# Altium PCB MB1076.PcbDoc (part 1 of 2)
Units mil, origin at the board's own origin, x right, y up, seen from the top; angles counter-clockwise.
Board outline 2200 x 4400 mil, 2 copper layers (TOP, Bottom), stack 60.433 mil thick; 144 components, 144 nets, 518 pads, 266 vias.
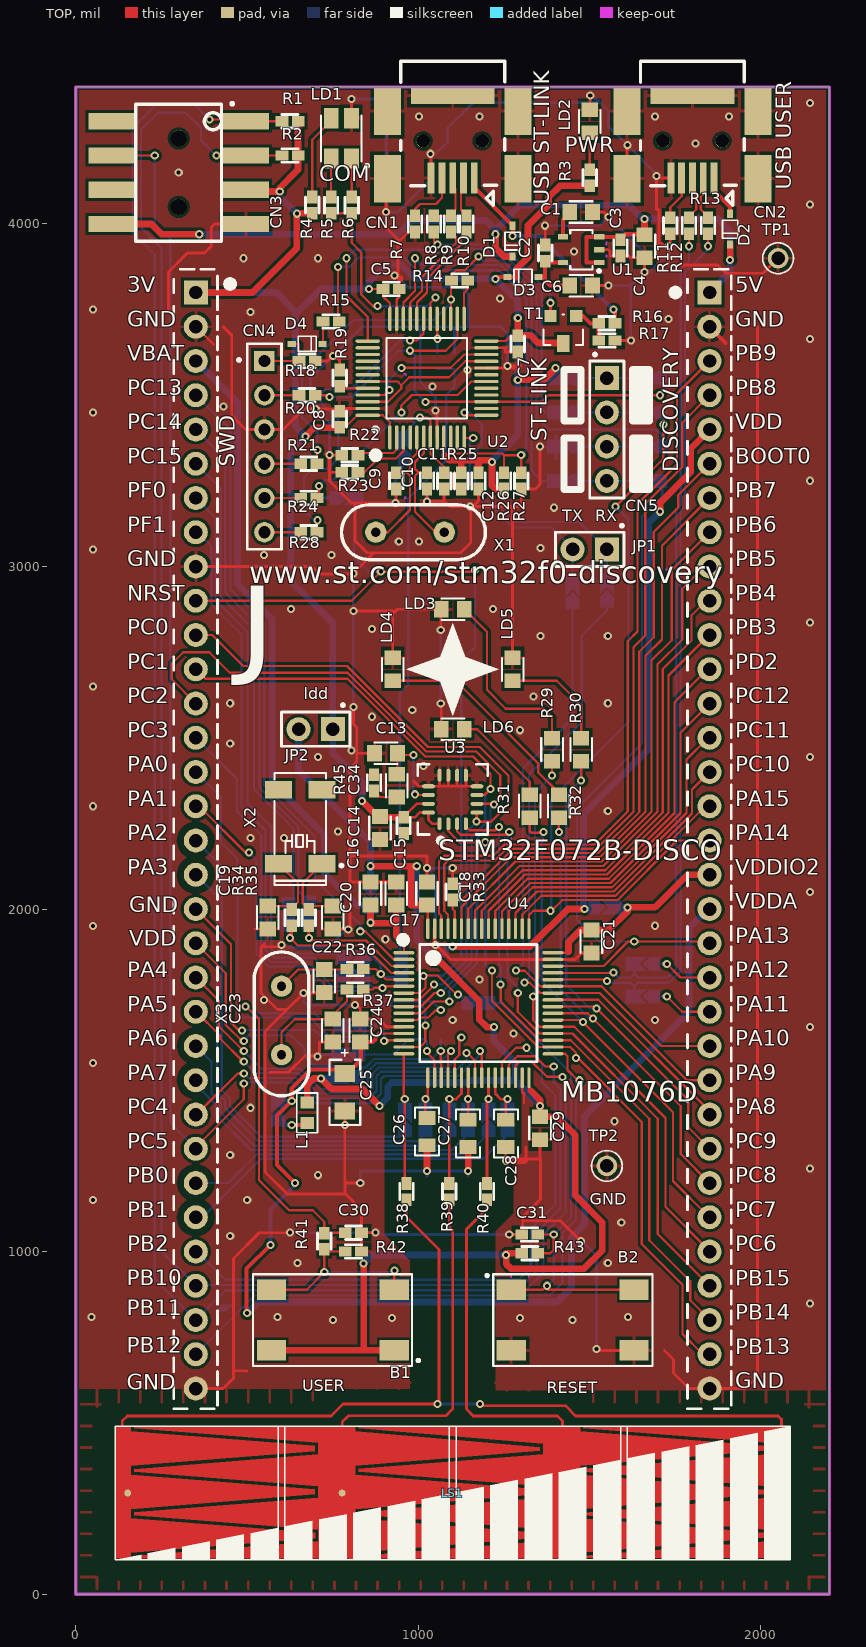
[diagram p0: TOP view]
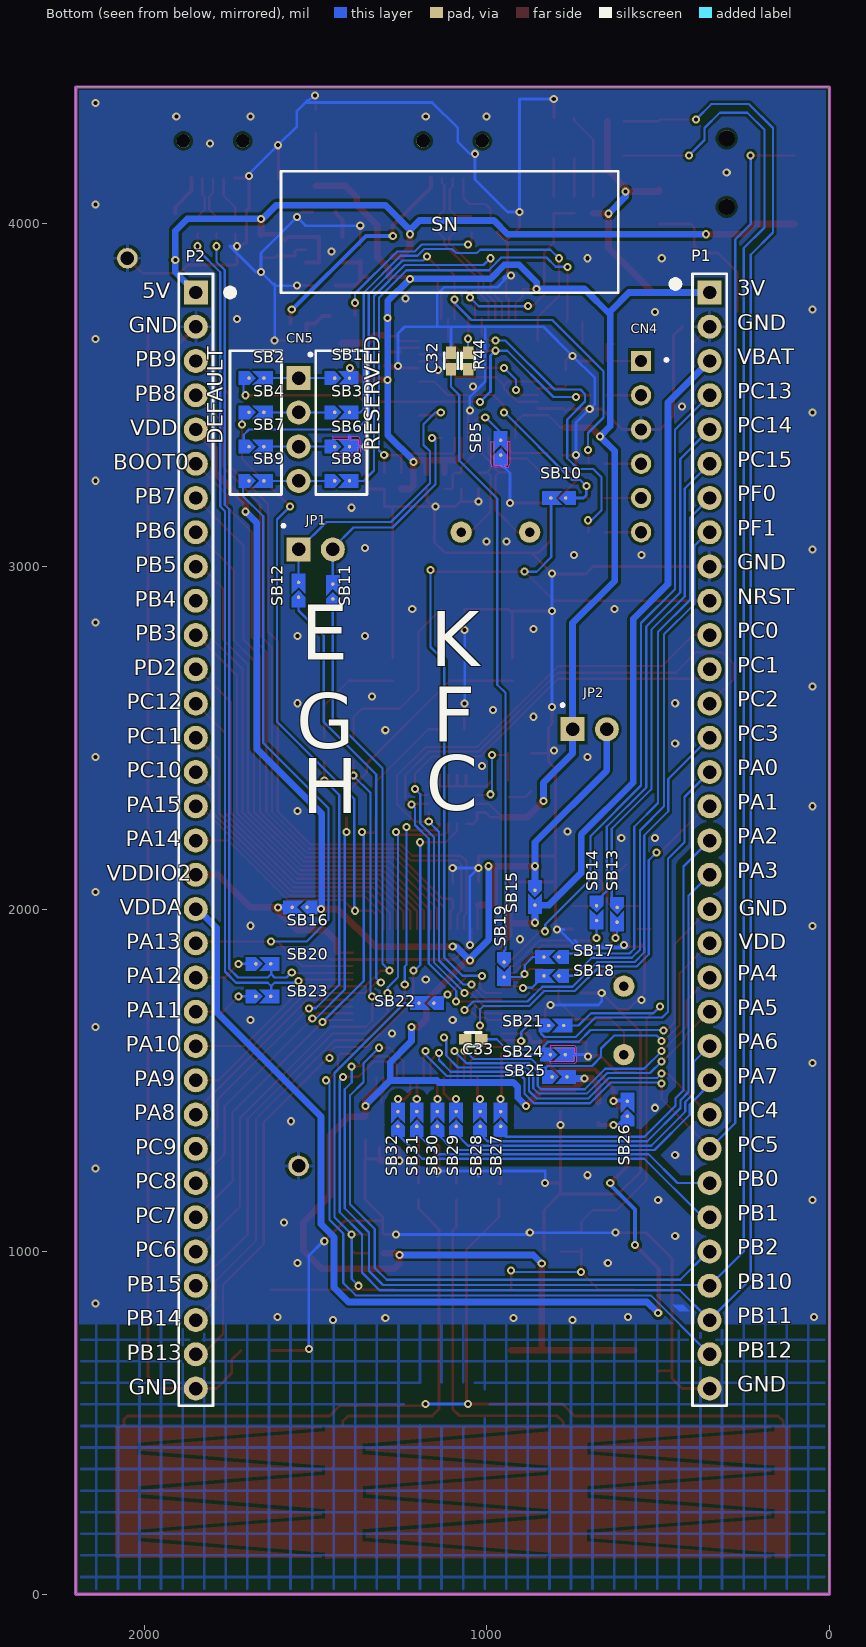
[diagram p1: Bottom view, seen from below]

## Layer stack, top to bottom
Top Mask: solder mask 0.4, Solder Resist, Dk 3.5
TOP: signal copper 1.3779
Dielectric 1: dielectric 57.6772, FR-4, Dk 4.8
Bottom: signal copper 1.3779
Bottom Solder: solder mask 0.4, Solder Resist, Dk 3.5

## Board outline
0,0 2200,0 2200,4400 0,4400

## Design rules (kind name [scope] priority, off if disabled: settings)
BoardOutlineClearance [All and not (IsPad and ((Name = 'CN1-6') or (Name = 'CN2-6') or (Name = 'CN1-7') or (Name = 'CN2-7'))) and not OnSilkscreen] p1: gap=10 ignorepadtopadclearanceinfootprint=FALSE except(0: Arc-SplitContinuation Track-SplitContinuation SMDPad-SplitContinuation THPad-SplitContinuation Via-SplitContinuation Fill-SplitContinuation Poly-SplitContinuation Region-SplitContinuation Text-SplitContinuation)
Clearance Clearance_Keepout [IsKeepout] p1: gap=0 ignorepadtopadclearanceinfootprint=FALSE
Clearance Clearance_ESPACE_0.5 [InNetClass('ESPACE_0.5') vs InPolygon] p2: gap=19.68 ignorepadtopadclearanceinfootprint=FALSE except(0: Arc-Hole Track-Hole SMDPad-Hole THPad-Hole Via-Hole Fill-Hole Poly-Hole Region-Hole Text-Hole)
Clearance Clearance_LS_P1 [InNet('LS_P1') vs InPolygon and OnBottomLayer] p3: gap=48.03 ignorepadtopadclearanceinfootprint=FALSE except(0: Arc-Hole Track-Hole SMDPad-Hole THPad-Hole Via-Hole Fill-Hole Poly-Hole Region-Hole Text-Hole; 55.91: Arc-Fill Arc-Poly Arc-Region Track-Fill Track-Poly Track-Region)
Clearance Clearance_CN1_CN2 [IsPad and ((Name = 'CN1-6') or (Name = 'CN2-6')) vs IsKeepout] p4: gap=0 ignorepadtopadclearanceinfootprint=FALSE
Clearance CopperToBoard [InPolygon vs IsBoardOutline] p5: gap=9.84 ignorepadtopadclearanceinfootprint=FALSE except(0: Arc-Hole Track-Hole SMDPad-Hole THPad-Hole Via-Hole Fill-Hole Poly-Hole Region-Hole Text-Hole)
Clearance "Clearance_Pont citroen" [HasFootprint('JP2_SMD (Primary)') and IsComponentPrimitive and IsRegion vs HasFootprint('JP2_SMD (Primary)') and IsComponentPrimitive and IsRegion] p6: gap=3.94 ignorepadtopadclearanceinfootprint=FALSE except(0: Arc-Hole Track-Hole SMDPad-Hole THPad-Hole Via-Hole Fill-Hole Poly-Hole Region-Hole Text-Hole)
Clearance [All] p7: gap=5.91 ignorepadtopadclearanceinfootprint=FALSE except(0: Arc-Hole Track-Hole SMDPad-Hole THPad-Hole Via-Hole Fill-Hole Poly-Hole Region-Hole Text-Hole; 6.93: Fill-Fill Fill-Poly Fill-Region Poly-Poly Poly-Region Region-Region; 8.27: Arc-Fill Arc-Poly Arc-Region Track-Fill Track-Poly Track-Region SMDPad-Fill SMDPad-Poly SMDPad-Region THPad-Fill THPad-Poly THPad-Region Via-Fill Via-Poly Via-Region)
ComponentClearance [All and not HasFootprint('VIA')] p1: gap=3.94 collisioncheckmode=3 verticalgap=10 showdistances=FALSE
MinimumSolderMaskSliver [All] p1: minsoldermaskwidth=3.94
PolygonConnect PolygonConnect_1 [IsPad and ((Name = 'P1-33') or (Name = 'P2-33'))] p1: connectstyle=Direct reliefconductorwidth=10 reliefentries=4 polygonreliefangle="90 Angle" airgapwidth=10
PolygonConnect "PolygonConnect_Via comp" [IsVia] p2: connectstyle=Direct reliefconductorwidth=10 reliefentries=4 polygonreliefangle="90 Angle" airgapwidth=10
PolygonConnect [All] p3: connectstyle=Relief reliefconductorwidth=10 reliefentries=4 polygonreliefangle="90 Angle" airgapwidth=10
RoutingVias [All] p1: holewidth=11.81 width=23.62 viastyle="Through Hole" minholewidth=11.81 minwidth=23.62 maxholewidth=11.81 maxwidth=23.62
SolderMaskExpansion SolderMaskExpansion_via [HasFootprint('via') or IsVia] p1: expansion=-39.37
SolderMaskExpansion [All] p2: expansion=1.97
Width [All] p1: maxlimit=78.74 minlimit=5.91 preferedwidth=6.5
28 further rules are at their usual default settings.

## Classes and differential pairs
component class MB1076C: P1 P2
component class U_MEMS_USB: C13 C14 C15 C34 CN2 CN3 D2 LD3 LD4 LD5 LD6 R1 R2 R11 R12 R13 R29 R30 R31 R32 R45 TP1 TP2 U3
component class U_SENSOR_PB: B1 B2 C26 C27 C28 C30 C31 LS1 R38 R39 R40 R41 R42 R43 SB21 SB22
component class U_ST_LINK: C1 C2 C3 C4 C5 C6 C7 C8 C9 C10 C11 C12 C32 CN1 CN4 CN5 D1 D3 D4 JP1 JP2 LD1 LD2 R3 R4 R5 R6 R7 R8 R9 R10 R14 R15 R16 R17 R18 R19 R20 R21 R22 R23 R24 R25 R26 R27 R28 R44 SB1 SB2 SB3 SB4 SB5 SB6 SB7 SB8 SB9 SB10 SB11 SB12 T1 U1 U2 X1
component class U_STM32Fx: C16 C17 C18 C19 C20 C21 C22 C23 C24 C25 C29 C33 L1 R33 R34 R35 R36 R37 SB13 SB14 SB15 SB16 SB17 SB18 SB19 SB20 SB23 SB24 SB25 SB26 SB27 SB28 SB29 SB30 SB31 SB32 U4 X2 X3
net class ESPACE_0.5: PA2 PA3 PA6 PA7 PB0 PB1 TS_G1_IO3 TS_G1_IO4 TS_G2_IO3 TS_G2_IO4 TS_G3_IO2 TS_G3_IO3

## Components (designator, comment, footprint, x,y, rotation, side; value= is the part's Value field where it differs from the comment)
B1 "SW-PUSH-CMS" BP1CMS 750,800 r90 top locked
B2 "SW-PUSH-CMS" BP1CMS 1450,800 r270 top
C1 "10nF_X7R_0603" 0603C 1475,4035 r180 top value=10NF
C2 "100nF" 0402C 1370,3915 r0 top
C3 "100nF" 0402C 1590,3930 r180 top
C4 "1µF_X5R_0603" 0603C 1660,3935 r90 top value=1µF
C5 "100nF" 0402C 920,3810 r270 top
C6 "1µF_X5R_0603" 0603C 1475,3820 r0 top value=1µF
C7 "100nF" 0402C 1290,3650 r180 top
C8 "100nF" 0402C 770,3430 r0 top
C9 "20pF" 0402C 935,3250 r0 top value=100nF
C10 "20pF" 0402C 1025,3250 r0 top value=100nF
C11 "100nF" 0402C 1075,3250 r180 top
C12 "100nF" 0402C 1175,3250 r180 top
C13 "10nF/25V" 0603C 905,2455 r0 top value=100nF
C14 "10uF" 0603C 887.8,2236.22 r90 top value=100nF
C15 "100nF" 0402C 956.69,2244.09 r180 top
C16 "1uF" 0603C 860,2045 r90 top
C17 "100nF" 0603C 935,2045 r270 top
C18 "100nF" 0603C 1025,2045 r90 top
C19 "6.8pF" 0603C 560,1975 r270 top
C20 "6.8pF" 0603C 750,1975 r270 top
C21 "100nF" 0603C 1505,1905 r90 top
C22 "20pF" 0603C 725,1790 r90 top
C23 "20pF" 0603C 750,1645 r90 top
C24 "100nF" 0603C 830,1645 r270 top
C25 "1uF" CASE-AA 785,1465 r90 top value=10uF
C26 "47nF" 0805C 1025,1350 r270 top
C27 "47nF" 0805C 1145,1345 r270 top
C28 "47nF" 0805C 1255,1345 r270 top
C29 "100nF" 0603C 1355,1360 r90 top
C30 "100nF" 0402C 810,1055 r270 top
C31 "100nF" 0402C 1325,1050 r90 top
C32 "20pF" 0402C 1105,3600 r180 bottom locked value=100nF
C33 "100nF" 0402C 1040,1620 r90 bottom locked
C34 "Capacitor" C0603 936.42,2360.24 r270 top value=470nF
CN1 "USB-MINI-typeB" USB-MINI-B-SMD 1100,4242.52 r0 top
CN2 "USB-MINI-typeB" USB-MINI-B-SMD 1800,4242.52 r0 top
CN3 "SSM-104-L-DH" SSM-104-L-DH 300,4150 r90 top
CN4 "Header 6" HDR1X6 550,3600 r270 top
CN5 "Header 4" "Header 4" 1550,3550 r270 top
D1 "BAT60JFILM" SOD323/A 1275,3950 r90 top
D2 "BAT60JFILM" SOD323/A 1910,3985 r90 top
D3 "BAT60JFILM" SOD323/A 1305,3845 r0 top
D4 "BAT60JFILM" SOD323/A 675,3650 r180 top
JP1 "JP2" SIP2/2.54 1550,3050 r180 top
JP2 "" SIP2/2.54 750,2525 r180 top
L1 "fcm1608-0603" 0603L 675,1405 r270 top value=100uH
LD1 "LD_BICOLOR_CMS" HSMF-A201 775,4250 r270 top
LD2 "LED, red" 0603D 1500,4300 r90 top
LD3 "LED, red" 0603D 1100,2875 r180 top
LD4 "LED, orange" 0603D 925,2700 r90 top
LD5 "LED, green" 0603D 1275,2700 r90 top
LD6 "LED, blue" 0603D 1100,2525 r180 top
LS1 "Linear Sensor" "Linear Sensor 3 electrodes" 1100,295 r0 top
P1 "Header 33" HDR1X33 350,3800 r270 bottom locked
P2 "Header 33" HDR1X33 1850,3800 r270 bottom locked
R1 "4K7" 0402R 625,4300 r90 top value=10K
R2 "4K7" 0402R 625,4200 r90 top value=10K
R3 "1K" 0402R 1500,4135 r0 top value=10K
R4 "0" 0402R 690,4055 r0 top value=10K
R5 "100" 0402R 745,4055 r180 top value=10K
R6 "100" 0402R 805,4055 r180 top value=10K
R7 "100K" 0402R 990,4000 r0 top value=10K
R8 "1K5" 0402R 1045,4000 r0 top value=10K
R9 "0" 0402R 1095,4000 r0 top value=10K
R10 "0" 0402R 1140,4000 r0 top value=10K
R11 "100K" 0402R 1735,3995 r0 top value=10K
R12 "0" 0402R 1790,3995 r0 top value=10K
R13 "0" 0402R 1845,3995 r0 top value=10K
R14 "100" 0402R 1120,3835 r270 top value=10K
R15 "[NA]" 0402R 745,3715 r90 top value=10K
R16 "10K" 0402R 1550,3710 r90 top
R17 "36K" 0402R 1550,3660 r270 top value=10K
R18 "10K" 0402R 675,3600 r90 top
R19 "100K" 0402R 770,3550 r0 top value=10K
R20 "22" 0402R 675,3500 r90 top value=10K
R21 "22" 0402R 680,3300 r90 top value=10K
R22 "10K" 0402R 800,3325 r90 top
R23 "[NA]" 0402R 800,3275 r90 top value=10K
R24 "22" 0402R 680,3200 r90 top value=10K
R25 "100K" 0402R 1125,3250 r180 top value=10K
R26 "4K7" 0402R 1250,3250 r180 top value=10K
R27 "4K7" 0402R 1300,3250 r180 top value=10K
R28 "22" 0402R 680,3100 r90 top value=10K
R29 "1K" 0603R 1390,2465 r90 top value=10K
R30 "330" 0603R 1475,2465 r90 top value=10K
R31 "510" 0603R 1325,2300 r90 top value=10K
R32 "1K" 0603R 1410,2300 r90 top value=10K
R33 "510" 0402R 1100,2050 r180 top value=10K
R34 "0" 0402R 630,1975 r180 top value=1K5
R35 "0" 0402R 680,1975 r180 top value=1K5
R36 "0" 0402R 815,1825 r270 top value=1K5
R37 "220" 0402R 815,1765 r270 top value=1K5
R38 "10K" 0402R 965,1175 r0 top
R39 "10K" 0402R 1090,1175 r0 top
R40 "10K" 0402R 1200,1175 r0 top
R41 "10K" 0402R 725,1030 r0 top
R42 "10K" 0402R 810,1000 r270 top
R43 "[NA]" 0402R 1325,995 r270 top value=10K
R44 "100" 0402R 1055,3600 r180 bottom locked value=10K
R45 "10K" 0402R 870.08,2368.11 r0 top
SB1 "Circuit Breaker" JP2_SMD 1425,3550 r180 bottom locked
SB2 "Circuit Breaker" JP2_SMD 1675,3550 r180 bottom locked
SB3 "Circuit Breaker" JP2_SMD 1425,3450 r180 bottom locked
SB4 "Circuit Breaker" JP2_SMD 1675,3450 r180 bottom locked
SB5 "Circuit Breaker" JP2_SMD 960,3345 r90 bottom locked
SB6 "Circuit Breaker" JP2_SMD 1425,3350 r180 bottom locked
SB7 "Circuit Breaker" JP2_SMD 1675,3350 r180 bottom locked
SB8 "Circuit Breaker" JP2_SMD 1425,3250 r180 bottom locked
SB9 "Circuit Breaker" JP2_SMD 1675,3250 r180 bottom locked
SB10 "Circuit Breaker" JP2_SMD 790,3200 r0 bottom locked
SB11 "Circuit Breaker" JP2_SMD 1450,2925 r90 bottom locked
SB12 "Circuit Breaker" JP2_SMD 1550,2930 r90 bottom locked
SB13 "Circuit Breaker" JP2_SMD 620,1985 r270 bottom locked
SB14 "Circuit Breaker" JP2_SMD 680,1990 r270 bottom locked
SB15 "Circuit Breaker" JP2_SMD 860,2035 r270 bottom locked
SB16 "Circuit Breaker" JP2_SMD 1545,2005 r0 bottom locked
SB17 "Circuit Breaker" JP2_SMD 810,1860 r0 bottom locked
SB18 "Circuit Breaker" JP2_SMD 810,1805 r0 bottom locked
SB19 "Circuit Breaker" JP2_SMD 950,1825 r270 bottom locked
SB20 "Circuit Breaker" JP2_SMD 1655,1840 r180 bottom locked
SB21 "Circuit Breaker" JP2_SMD 800,1660 r180 bottom locked
SB22 "Circuit Breaker" JP2_SMD 1175,1725 r0 bottom locked
SB23 "Circuit Breaker" JP2_SMD 1655,1745 r180 bottom locked
SB24 "Circuit Breaker" JP2_SMD 795,1575 r180 bottom
SB25 "Circuit Breaker" JP2_SMD 790,1510 r180 bottom locked
SB26 "Circuit Breaker" JP2_SMD 590,1415 r90 bottom locked
SB27 "Circuit Breaker" JP2_SMD 960,1385 r90 bottom locked
SB28 "Circuit Breaker" JP2_SMD 1020,1385 r90 bottom locked
SB29 "Circuit Breaker" JP2_SMD 1090,1385 r90 bottom locked
SB30 "Circuit Breaker" JP2_SMD 1145,1385 r90 bottom locked
SB31 "Circuit Breaker" JP2_SMD 1205,1385 r90 bottom locked
SB32 "Circuit Breaker" JP2_SMD 1260,1385 r90 bottom locked
T1 "9013-SOT23" SOT-23 1422.83,3691.34 r90 top
TP1 "Test point 1 pin with hole" SIP1/2.54 2050,3900 r90 top
TP2 "Test point 1 pin with hole" SIP1/2.54 1550,1250 r270 top
U1 "LD3985M33R" SOT-23-5L 1475,3925 r180 top
U2 "STM32F103C8T6" "QFP48 7X7" 1025,3550 r90 top
U3 "I3G4250D" ICC_LGA16_4X4_P065_H1P1 1100,2320 r90 top locked
U4 "STM32F072RBT6" QFP64 1175,1725 r0 top
X1 "8MHz" XTAL1 1075,3100 r180 top
X2 "MC306-G-06Q-32.768" MC306-CRYSTAL 655,2240 r90 top
X3 "8MHz" XTAL1 600,1575 r90 top

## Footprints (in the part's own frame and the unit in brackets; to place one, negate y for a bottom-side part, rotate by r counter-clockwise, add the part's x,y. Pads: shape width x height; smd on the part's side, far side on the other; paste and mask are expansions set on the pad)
0402C [mil]
  rect 30x37 smd paste+0 mask+3.94: 1(0,23.62) 2(0,-23.62)
  silkscreen extent -20,-23 20,24
0402R [mil]
  rect 30x37 smd paste+0 mask+3.94: 1(0,23.62) 2(0,-23.62)
  silkscreen extent -20,-23 20,24
0603C [mm]
  rect 1.1x1.2 smd paste+0 mask+0.1: 1(-0.85,0) 2(0.85,0)
  silkscreen extent -0.85,-0.8 0.86,0.8
0603D [mm]
  rect 1.1x1.2 smd paste+0 mask+0.1: 1(-0.85,0) 2(0.85,0)
  silkscreen extent -0.86,-0.8 0.84,0.8
0603L [mil]
  rect 35x40 smd paste+0 mask+3.94: 1(-30,0) 2(30,0)
  silkscreen extent -58,-30 58,30
0603R [mm]
  rect 1.1x1.2 smd paste+0 mask+0.1: 1(-0.85,0) 2(0.85,0)
  silkscreen extent -0.85,-0.8 0.86,0.8
0805C [mil]
  rect 40x50 smd paste+0 mask+3.94: 1(40,0) 2(-40,0)
  silkscreen extent -70,-35 70,35
BP1CMS [mm]
  rect 1.52x2.16 smd paste+0 mask+0.1: 1(-2.25,-4.55) 2(2.25,-4.55) 3(2.25,4.55) 4(-2.25,4.55)
  silkscreen extent -3.4,-5.88 3.4,5.92
C0603 [mm]
  rect 1.1x1.2 smd paste+0 mask+0.1: 1(-0.85,0) 2(0.85,0)
  silkscreen extent -0.85,-0.8 0.86,0.8
CASE-AA [mil]
  rect 50x60 smd paste+0 mask+3.94: 1(55,0) 2(-55,0)
  silkscreen extent -95,-45 126,45
HDR1X6 [mm] "Connector; Header; 6 Position"
  rect 1.5x1.5 hole 0.9: 1(0,0)
  round 1.5 hole 0.9: 2(2.54,0) 3(5.08,0) 4(7.62,0) 5(10.16,0) 6(12.7,0)
  silkscreen extent -1.27,-1.27 13.97,1.27
HDR1X33 [mil]
  rect 70x70 / inner round 0 / far side rect 70x70 hole 39.37 paste+0 mask+3.94: 1(0,0)
  round 70 / inner round 0 / far side round 70 hole 39.37 paste+0 mask+3.94: 2(100,0) 3(200,0) 4(300,0) 5(400,0) 6(500,0) 7(600,0) 8(700,0) 9(800,0) 10(900,0) 11(1000,0) 12(1100,0) 13(1200,0) 14(1300,0) 15(1400,0) 16(1500,0) 17(1600,0) 18(1700,0) 19(1800,0) 20(1900,0) 21(2000,0) 22(2100,0) 23(2200,0) 24(2300,0) 25(2400,0) 26(2500,0) 27(2600,0) 28(2700,0) 29(2800,0) 30(2900,0) 31(3000,0) 32(3100,0) 33(3200,0)
  silkscreen extent -55,-50 3250,50
"Header 4" [mil]
  rect 70x70 / inner round 0 / far side rect 70x70 hole 39.37 paste+0 mask+3.94: 1(0,0)
  round 70 / inner round 0 / far side round 70 hole 39.37 paste+0 mask+3.94: 2(100,0) 3(200,0) 4(300,0)
  silkscreen extent -50,-50 350,50
HSMF-A201 [mm]
  rect 1.5x1.1 smd paste+0 mask+0.1: 1(-1.5,0.75) 2(1.5,0.75) 3(1.5,-0.75) 4(-1.5,-0.75)
  silkscreen extent -1.7,-1.5 1.7,1.5
ICC_LGA16_4X4_P065_H1P1 [mm]
  oval 0.95x0.3 smd paste+0 mask+0.1: 1(-1.8,0.975) 2(-1.8,0.325) 3(-1.8,-0.325) 4(-1.8,-0.975) 9(1.8,-0.975) 10(1.8,-0.325) 11(1.8,0.325) 12(1.8,0.975)
  oval 0.3x0.95 smd paste+0 mask+0.1: 5(-0.975,-1.8) 6(-0.325,-1.8) 7(0.325,-1.8) 8(0.975,-1.8) 13(0.975,1.8) 14(0.325,1.8) 15(-0.325,1.8) 16(-0.975,1.8)
  silkscreen extent -3.18,-2.6 2.6,2.6
JP2_SMD [mil]
  round 10 smd paste-10 mask+3.94: 1(-19.68,0) 2(23.62,0)
  TOP region: -19.68,19.68 -49.21,19.68 -49.21,-19.69 -19.68,-19.69 0,0
  TOP region: -9.84,-19.69 49.21,-19.69 49.21,19.68 -9.84,19.68 9.84,0
"Linear Sensor 3 electrodes" [mil]
  round 20 smd paste-20 mask-20: 1(-948.82,0) 2(-322.84,0) 3(322.83,0)
  round 28 smd paste-28 mask-28: 1(948.82,0)
  TOP region: -930.47,189.31 -930.47,195.28 -284.02,195.55 -284.02,180.32 253.82,133.98 253.82,122.83 -283.98,80.07 -283.98,53.15 253.15,10.63 253.15,-3.94 -283.98,-46.97 -283.98,-73.58 253.23,-115.87 253.23,-130.83 -284.02,-173.92 -284.02,-191.36 -302.41,-191.36 -930.47,-190.94 -930.47,-183.46 -391.89,-140.94 -391.89,-106.69 -930.47,-64.29 -930.47,-56.81 -392.09,-13.78 -392.09,20.08 -930.47,62.6 -930.47,70.08 -392.28,112.99 -392.28,146.85
  TOP region: -273.68,189.78 -273.68,195 371.65,195 371.65,180 910.15,137.6 910.15,122.83 371.65,79.53 371.65,52.76 909.45,9.84 909.45,-4.33 371.65,-48.03 371.65,-74.02 908.9,-116.53 908.9,-131.1 371.65,-174.41 371.65,-191.34 358.32,-191.34 -273.78,-190.75 -273.78,-183.27 263.48,-140.55 263.48,-106.33 -273.78,-64.17 -273.78,-56.3 263.23,-13.38 263.23,20.08 -273.78,62.6 -273.78,70.47 264.02,113.39 264.02,143.31
  TOP region: -985,195 -985,-190.55 -940.68,-190.55 -940.68,-174 -401.97,-131.5 -401.97,-116.14 -940.55,-73.62 -940.55,-47.64 -402.37,-4.33 -402.37,10.63 -940.55,53.15 -940.55,79.53 -402.37,122.44 -402.37,137.4 -940.71,179.92 -940.68,195
  TOP region: 381.73,189.37 381.73,195 985,195 985,-190 381.73,-189.37 381.73,-183.66 919.53,-140.94 919.53,-107.09 381.73,-64.76 381.73,-57.28 919.53,-13.78 919.53,19.29 381.73,62.01 381.73,70.28 920.32,113.39 920.32,146.85
  silkscreen extent -985,-195 985,195
MC306-CRYSTAL [mm]
  rect 1.3x2 smd paste+0 mask+0.1: 1(-2.75,-1.6) 2(2.75,-1.6) 3(2.75,1.6) 4(-2.75,1.6)
  silkscreen extent -4.3,-1.9 4,1.9
"QFP48 7X7" [mm]
  oval 1.803x0.257 smd paste+0 mask+0.1: 1(-4.4,2.75) 12(-4.4,-2.75) 25(4.4,-2.75) 36(4.4,2.75)
  oval 1.803x0.254 smd paste+0 mask+0.1: 2(-4.4,2.25) 3(-4.4,1.75) 4(-4.4,1.25) 5(-4.4,0.75) 6(-4.4,0.25) 7(-4.4,-0.25) 8(-4.4,-0.75) 9(-4.4,-1.25) 10(-4.4,-1.75) 11(-4.4,-2.25) 26(4.4,-2.25) 27(4.4,-1.75) 28(4.4,-1.25) 29(4.4,-0.75) 30(4.4,-0.25) 31(4.4,0.25) 32(4.4,0.75) 33(4.4,1.25) 34(4.4,1.75) 35(4.4,2.25)
  oval 0.257x1.803 smd paste+0 mask+0.1: 13(-2.75,-4.4) 24(2.75,-4.4) 37(2.75,4.4) 48(-2.75,4.4)
  oval 0.254x1.803 smd paste+0 mask+0.1: 14(-2.25,-4.4) 15(-1.75,-4.4) 16(-1.25,-4.4) 17(-0.75,-4.4) 18(-0.25,-4.4) 19(0.25,-4.4) 20(0.75,-4.4) 21(1.25,-4.4) 22(1.75,-4.4) 23(2.25,-4.4) 38(2.25,4.4) 39(1.75,4.4) 40(1.25,4.4) 41(0.75,4.4) 42(0.25,4.4) 43(-0.25,4.4) 44(-0.75,4.4) 45(-1.25,4.4) 46(-1.75,4.4) 47(-2.25,4.4)
  silkscreen extent -3.96,-2.98 2.97,3.96
QFP64 [mm]
  oval 1.55x0.25 smd paste+0 mask+0.1: 1(-5.525,3.75) 2(-5.525,3.25) 3(-5.525,2.75) 4(-5.525,2.25) 5(-5.525,1.75) 6(-5.525,1.25) 7(-5.525,0.75) 8(-5.525,0.25) 9(-5.525,-0.25) 10(-5.525,-0.75) 11(-5.525,-1.25) 12(-5.525,-1.75) 13(-5.525,-2.25) 14(-5.525,-2.75) 15(-5.525,-3.25) 16(-5.525,-3.75) 33(5.525,-3.75) 34(5.525,-3.25) 35(5.525,-2.75) 36(5.525,-2.25) 37(5.525,-1.75) 38(5.525,-1.25) 39(5.525,-0.75) 40(5.525,-0.25) 41(5.525,0.25) 42(5.525,0.75) 43(5.525,1.25) 44(5.525,1.75) 45(5.525,2.25) 46(5.525,2.75) 47(5.525,3.25) 48(5.525,3.75)
  oval 0.25x1.55 smd paste+0 mask+0.1: 17(-3.75,-5.525) 18(-3.25,-5.525) 19(-2.75,-5.525) 20(-2.25,-5.525) 21(-1.75,-5.525) 22(-1.25,-5.525) 23(-0.75,-5.525) 24(-0.25,-5.525) 25(0.25,-5.525) 26(0.75,-5.525) 27(1.25,-5.525) 28(1.75,-5.525) 29(2.25,-5.525) 30(2.75,-5.525) 31(3.25,-5.525) 32(3.75,-5.525) 49(3.75,5.525) 50(3.25,5.525) 51(2.75,5.525) 52(2.25,5.525) 53(1.75,5.525) 54(1.25,5.525) 55(0.75,5.525) 56(0.25,5.525) 57(-0.25,5.525) 58(-0.75,5.525) 59(-1.25,5.525) 60(-1.75,5.525) 61(-2.25,5.525) 62(-2.75,5.525) 63(-3.25,5.525) 64(-3.75,5.525)
  silkscreen extent -5.65,-4.35 4.35,4.55
SIP1/2.54 [mil]
  round 60 / inner round 0 / far side round 60 hole 39.37 paste+0 mask+3.94: 1(0,0)
  silkscreen extent -45,-45 45,45
SIP2/2.54 [mil]
  rect 70x70 / inner round 0 / far side rect 70x70 hole 39.37 paste+0 mask+3.94: 1(0,0)
  round 70 / inner round 0 / far side round 70 hole 39.37 paste+0 mask+3.94: 2(100,0)
  silkscreen extent -50,-50 150,50
SOD323/A [mm]
  rect 0.6x0.45 smd paste+0 mask+0.1: 1(1.143,0) 2(-1.143,0)
  silkscreen extent -0.67,-0.57 0.67,0.57
SOT-23 [mil]
  rect 36x36 smd paste+0 mask+3.92: 1(40,-37.5) 2(40,37.5)
  rect 50x36 smd paste+0 mask+3.92: 3(-40,0.5)
  silkscreen extent -45,-58 45,58
SOT-23-5L [mil]
  rect 30x16 smd paste+0 mask+3.94: 1(-53.15,37.4) 2(-53.15,0) 3(-53.15,-37.4) 4(53.15,-37.4) 5(53.15,37.4)
  silkscreen extent -33,-58 32,57
SSM-104-L-DH [mm]
  rect 1.2x3.4 smd paste+0 mask+0.1: 1(3.81,-5) 2(3.81,5) 3(1.27,-5) 4(1.27,5) 5(-1.27,-5) 6(-1.27,5) 7(-3.81,-5) 8(-3.81,5)
  round 1.168 / inner round 0 / far side round 1.168 hole 1.2 unplated paste+0 mask+0.232: 9(2.54,0) 10(-2.54,0)
  silkscreen extent -5.08,-3.18 5.08,3.18
USB-MINI-B-SMD [mm]
  rect 0.508x2.3 smd paste+0 mask+0.1: 1(1.597,-2.75) 2(0.797,-2.75) 3(-0.003,-2.75) 4(-0.803,-2.75) 5(-1.603,-2.75)
  rect 2x3.5 smd paste+0 mask+0.1: 6(-4.853,-2.8) 6(-4.853,2.2) 6(4.847,-2.8) 6(4.847,2.2)
  rect 6.2x1.2 smd paste+0 mask+0.1: 6(0,3.35)
  round 1 / inner round 0 / far side round 1 hole 1 unplated paste+0 mask+0.1: 11(2.194,0) 12(-2.2,0)
  silkscreen extent -3.85,-4.76 3.85,5.9
XTAL1 [mil]
  round 62 / inner round 0 / far side round 62 hole 27.56 paste+0 mask+3.94: 1(-0.36,-0.2) 2(199.64,-0.2)
  silkscreen extent -120,-80 300,80

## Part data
B1 B2: "Non-Open Push-Button 0.1A 24V", Manuf_1=FARNELL, Manuf_Part_1=535-930
C1: library part "CAP SMD 0603  X7R 10000PF 50V 10%", "0603  X7R 10NF", Rated voltage=50V, Temperature Max=+125°C, Temperature Min=-55°C, Tolerance=10%
C2 C3 C5 C7 C8 C9 C10 C11 C12 C15 C30 C31 C32 C33: library part Capacitor_ST, "Capacitor 0402 / 0603 / 0805"
C4 C6: library part "CAP SMD 0603  X5R 1µF 25V 10%", "0603  X5R 1µF", Rated voltage=25V, Temperature Max=+125°C, Temperature Min=-55°C, Tolerance=10%
C13 C14 C16 C19 C20 C22 C23: library part CAP, "Capacitor"
C17 C18 C21 C24 C29: library part Cap, "Capacitor"
C25: library part "Cap Pol1", "Polarized Capacitor (Radial)"
C26 C27 C28: library part Cap_47nF_NPO_5%, "Capacitor 47nF,5%,25V,NPO,0805 Kemet", Manuf_1=Kemet, Manuf_Part_1=C0805C473J3GACTU
C34: library part MCD-01006, "Capacitor, MLCC, 470nF, 16V, X7R, 10%, 0603, T=0.8mm", Manufacturer=YAGEO, Manufacturer_Part_Number=CC0603KRX7R7BB474, Package=C0603
CN1: library part "USB-MINI-typeB connector", "USB-MINI-typeB connector", Manuf_2=lyconn, Manuf_Part_1=5075BMR-05-SM, Manuf_Part_2=218205M1110T
CN2: library part "USB-MINI-typeB connector", "USB-MINI-typeB connector", Manuf_Part_1=5075BMR-05-SM
CN3: "Header, 5-Pin, Dual row"
CN4: "Header, 6-Pin"
CN5: "Header, 4-Pin"
D1 D2 D3 D4: Manuf_1=STM
JP2: library part JP2
L1: library part Inductor, "Inductor"
LD1: "Bicolor Led", Manuf_1="Avago Technologies", Manuf_2=everluck, Manuf_Part_1=HSMF-A201-A00J1, Manuf_Part_2=LE-RGW35280
LD2 LD3: library part LED_red, "LED, red, 0603", Manuf_1=everlight, Manuf_Part_1=19-213-R6C-AP1Q2B/3T
LD4: library part LED_orange, "LED, orange, 0603", Manuf_1=everlight, Manuf_Part_1=19-217/S2C-AM2N2VY/3T
LD5: library part LED_green, "LED, green, 0603", Manuf_1=everlight, Manuf_Part_1=19-213SYGC/S530-E2/TR8
LD6: library part LED_blue, "LED, blue, 0603", Manuf_1=everlight, Manuf_Part_1=19-217/BHC-ZL1M2RY/3T
LS1: library part "Linear Sensor 3 pos", "plan de cuivre recouvert de vernis + Couche Plastic"
P1 P2: "Header, 33-Pin"
R1 R2 R3 R4 R5 R6 R7 R8 R9 R10 R11 R12 R13 R14 R15 R16 R17 R18 R19 R20 R21 R22 R23 R24 R25 R26 R27 R28 R29 R30 R31 R32 R33 R38 R39 R40 R41 R42 R43 R44 R45: library part Resistor_ST, "Resistor 0402 / 0603 / 0805"
R34 R35 R36 R37: library part res1, "Resistor"
T1: "NPN Bipolar Transistor"
TP1 TP2: library part TP1, "Test Point"
U1: "Ultra low drop-low noise BiCMOS voltage, regulators low ESR capacitors compatible", Manuf_1=STM
U2: "Medium-density performance line ARM-based 32-bit MCU with 64KB Flash", Manuf_1=STM
U3: library part MCD-01963, "MEMS motion sensor: 3-axis digital output gyroscope LG4-16 4x4mm", Manufacturer=STMICROELECTRONICS, Package=LGA-16
U4: "ARM-based 32-bit MCU (STM32-STINGRAY-128K-USB)", Manuf_1=STM
X1 X3: library part XTAL, "Crystal Oscillator,8Mhz,20PF,20PPM,-10-70 degree,DIP,HC-49S", Manuf_Part_1=9SL8000020AFXHF0
X2: library part XTAL_32K, "Crystal oscillator for clock,32.768K,6PF,20PPM,-40~85 degree,SMT", Manuf_1=JFVNY, Manuf_Part_1=ETMB32.768W060BMPF

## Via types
v1: diameter 23.62, hole 11.81, TOP to Bottom, 186 vias
v2: diameter 23.62, hole 11.81, TOP to Bottom, tented both sides, 80 vias

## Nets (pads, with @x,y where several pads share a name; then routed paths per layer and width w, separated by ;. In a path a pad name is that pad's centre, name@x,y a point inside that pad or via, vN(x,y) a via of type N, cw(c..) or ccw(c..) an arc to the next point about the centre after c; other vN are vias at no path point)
3V: C5.2 C7.2 C8.2 C12.2 C14.2 C15.2 CN3.5 D3.2 JP2.1 P1.1 R1.2 R2.2 R3.2 R4.2 R25.2 R26.1 SB1.2 T1.3 U2.1 U2.9 U2.24 U2.36 U2.48 U3.1 U3.15 U3.16 | length 6167.4
  TOP w6.5: C8.2@770,3406.38 785.88,3406.38 821.23,3441.73 U2.48@851.77,3441.73 895.77,3441.73 916.73,3420.77 U2.1@916.73,3376.77 ; v1(855,3810) C5.2@896.38,3810 896.38,3788.62 916.74,3768.26 U2.36@916.74,3723.23 ; U3.15@1020,2307.2 U3.15@1029.13,2307.2 ; U3.1@1060,2249.13 U3.1@1061.61,2249.13 ; U2.9@1074.21,3376.77 1074.21,3325.79 1075,3325 ; U2.24@1198.23,3658.27 1254.27,3658.27 1268,3672 1290,3672 C7.2@1290,3673.62
  TOP w7.87: C14.2@880.31,2269.69 C14.2@887.8,2269.69 C14.2@889.76,2267.72 ; U3.15@1020,2307.2 994.61,2307.2 956.69,2269.28 C15.2@956.69,2267.72 989.6,2267.72 1003.5,2281.61 U3.16@1029.13,2281.61 1029.13,2260 1040,2249.13 U3.1@1060,2249.13
  TOP w11.81: v1(1225,3840) 1230,3845 D3.2@1260,3845 1285,3845 1285.25,3845.25
  TOP w19.68: P1.1@350,3800 515,3800 645,3930 v1(645,4030) 645,4031.38 R4.2@690,4031.38 ; CN3.5@496.85,4100 496.85,4095 v1(595,4095) 595,4105 648.62,4158.62 R1.2@648.62,4300 ; v1(670,3380) 695,3405 770,3405 C8.2@770,3406.38 ; v1(835,2315) C14.2@880.31,2269.69 ; C14.2@889.76,2267.72 C15.2@956.69,2267.72 ; 1075,3325 1090,3310 1125,3310 ; R25.2@1125,3273.62 1125,3310 ; C12.2@1175,3273.62 1175,3310 ; v1(1215,3305) v1@1215,3304.5 ; R26.1@1250,3226.38 1225,3226.38 1215,3236.38 v1@1215,3304.5 ; 1285.25,3845.25 1285.25,3867.75 1320,3902.5 1320,3996 1380,4056 1380,4078 1413.38,4111.38 R3.2@1500,4111.38 ; v1(1290,3545) 1366.5,3545 1400,3578.5 v1(1400,3580) ; C7.2@1290,3673.62 C7.2@1290,3675.5 ; v1(1290,3725) C7.2@1290,3675.5 ; T1.3@1422.33,3651.34 1422.33,3652.5 1349.5,3652.5 1326.5,3675.5 C7.2@1290,3675.5 ; 1125,3310 1175,3310 ; 1175,3310 1209.5,3310 v1@1215,3304.5
  Bottom w19.68: P1.1@350,3800 585,3800 640,3745 640,3735 ; v1(595,4095) 595,4080 v1(645,4030) ; v1(835,2315) 835,2369 750,2454 JP2.1@750,2525 750,2835 627,2958 627,3337 v1(670,3380) 640,3410 640,3735 ; v1(1215,3305) 1215,3309 1290,3384 v1(1290,3545) v1(1290,3725) 1290,3775 v1(1225,3840) 990,3840 949,3881 906,3881 855,3830 v1(855,3810) 715,3810 640,3735 ; v1(1400,3580) 1401.38,3580 SB1.2@1401.38,3550
5V: C3.2 C4.2 CN3.8 D1.2 D2.2 P2.1 U1.1 U1.3 | length 2612.1
  TOP w11.81: U1.1@1528.15,3887.6 1490,3887.6 1490,3962.4 U1.3@1528.15,3962.4 1581.22,3962.4 C3.2@1590,3953.62 1590,3955 1605,3970 C4.2@1660,3970
  TOP w19.68: CN3.8@103.15,4000 220,4000 250,3970 v1(360,3970) ; v1(1225,3970) 1225,3929.5 1249.5,3905 D1.2@1275,3905 ; C4.2@1660,3968.47 1660,3970 v1(1660,4015) ; v1(1910,3895) D2.2@1910,3940
  Bottom w19.68: v1(360,3970) 940,3970 980,4010 1197.5,4010 1224.5,3983 1225,3983 ; v1(1225,3970) 1225,3983 ; P2.1@1850,3800 1910,3860 v1(1910,3895) 1910,3980 1875,4015 v1(1660,4015) 1655,4015 1615,4055 1297,4055 1225,3983
AIN_1: R15.2 R26.2 R27.2 U2.10 | length 1592.4
  TOP w6.5: v1(765,3875) 765,3718.62 R15.2@768.62,3715 ; U2.10@1093.9,3376.77 1093.9,3336.1 1100,3330 1245,3330 1250,3325 ; R26.2@1250,3273.62 1250,3325 ; R27.2@1300,3273.62 v1(1300,3325) 1250,3325
  Bottom w6.5: v1(765,3875) 799,3875 826,3902 958,3902 995,3865 1235,3865 1315,3785 1315,3338.5 1301.5,3325 v1(1300,3325)
B_USER: P1.15 SB21.1 U4.14 | length 1352.3
  TOP w6.5: v1(900,1615) 900,1616.73 U4.14@957.48,1616.73
  Bottom w6.5: P1.15@350,2400 423,2327 423,2195 471.5,2146.5 471.5,1700 488,1683.5 683.5,1683.5 740.5,1626.5 832,1626.5 842,1636.5 842,1660 ; SB21.1@819.68,1660 842,1660 ; v1(900,1615) 900,1641 881,1660 842,1660
BOOT0: P2.6 R33.1 U4.60 | length 1839.4
  TOP w6.5: U4.60@1106.1,1942.52 1106.1,1993.9 1100,2000 R33.1@1100,2026.38 1103.62,2030 1130,2030 1263.5,2163.5 1525.09,2163.5 1644.5,2282.91 1644.5,2751 1687,2793.5 1687,3100.5 1758.5,3172 1758.5,3208.5 P2.6@1850,3300
EXT_RESET: CN3.4 P1.26 U4.25 | length 4226.3
  TOP w6.5: CN3.4@103.15,4200 225,4200 230,4205 v1(230,4200) ; P1.26@350,1300 350,1304.5 490,1444.5 v1(490,1490) ; v1(1180,1585) 1184.84,1585 U4.25@1184.84,1507.48
  Bottom w6.5: v1(230,4200) 230,4000 275,3955 275,1375 P1.26@350,1300 ; v1(490,1490) 490,1493.5 639,1493.5 699.5,1433 862.5,1433 890.5,1461 890.5,1503.5 899.5,1512.5 1117.5,1512.5 1180,1575 v1(1180,1585)
GND: B2.2 B2.3 C1.1 C2.1 C3.1 C4.1 C5.1 C6.2 C7.1 C8.1 C9.2 C10.2 C11.1 C12.1 C13.1 C14.1 C15.1 C16.2 C17.1 C18.2 C19.2 C20.2 C21.1 C22.1 C23.1 C24.1 C25.2 C26.1 C27.1 C28.1 C29.1 C30.1 C31.1 C32.1 CN1.5 CN1.6 CN2.5 CN2.6 CN3.7 CN4.3 LD1.1 LD2.2 LD3.2 LD4.2 LD5.2 LD6.2 P1.2 P1.9 P1.33 P2.2 P2.33 R7.2 R11.2 R17.1 R18.2 R19.1 R22.1 R23.1 R27.1 R33.2 R42.1 R45.1 SB5.1 SB6.2 SB24.2 TP1.1 TP2.1 U1.2 U2.8 U2.20 U2.23 U2.35 U2.47 U3.8 U3.9 U3.10 U3.11 U3.12 U3.13 U4.12 U4.31 U4.47 U4.63 | length 23569.9
  TOP w6.5: P1.2@350,3700 402,3648 ; 522.22,1941.54 C19.2@560,1941.53 ; 1302.95,1464.5 1303.5,1464.5 1307.8,1460.2 ; U4.31@1302.95,1507.48 1302.95,1466.34 1307.8,1461.5 ; 1307.8,1434.65 1307.8,1460.2 ; 1307.8,1464.5 1307.8,1461.5 ; 1307.8,1460.2 1307.8,1461.5
  TOP w7.87: 1253.5,3638.58 1253.5,3626.38 C7.1@1290,3626.38 ; 1290,3579.53 1290,3585 1290,3598.04
  TOP w8.27: 270,3745 270,3860 325,3915 375,3915 395,3935 395,3990 405,4000 CN3.7@496.85,4000 ; P1.33@350,600 430,600 460,630 460,652 ; P1.9@350,3000 689.5,3000 711.5,2978 810,2978 v1(810,2980) 870,3040 ; 430,3700 455,3675 455,3440 495,3400 CN4.3@550,3400 605,3400 665,3460 v1(700,3460) 763.62,3460 C8.1@770,3453.62 777.8,3461.42 U2.47@851.77,3461.42 ; 498.5,651.5 494,651.5 493.5,652 460,652 ; 550,1897.5 542.5,1890 ; 567.5,1522.5 566.5,1523.5 621,1523.5 670,1572.5 674.5,1572.5 ; v1@600,1890 v1(600,1895) 595,1895 595,1890 542.5,1890 ; v1(625,1055) 535,1055 460,980 460,652 ; R18.2@698.62,3600 735,3600 v1(750,3615) 750,3621.28 770,3601.28 R19.1@770,3573.62 ; v1(705,1570) 675,1570 674.5,1569.5 674.5,1572.5 ; C22.1@725,1756.53 723.46,1755 v1(665,1755) 616.5,1706.5 ; C23.1@750,1611.53 710.63,1611.54 710.63,1582.13 701.75,1573.25 701,1572.5 674.5,1572.5 ; C20.2@750,1941.53 791.53,1941.54 792.5,1942.5 v1@795,1945 ; R23.1@776.38,3275 740,3275 ; R22.1@776.38,3325 v1(740,3325) 740,3275 ; C25.2@785,1410 v1(785,1370) 785,1210.5 785.5,1210 785.5,1200 ; v1(795,1940) 790,1940 v1@795,1945 ; LD1.1@804.53,4309.06 804.53,4365 v1(805,4365) ; v1(810,2590) 810,2540 820,2530 820,2455 ; v1(810,2870) 925,2870 925,2862 ; v1(815,1720) 816.5,1721.5 830,1708 C24.1@830,1678.47 884,1678.47 906.36,1656.1 U4.12@957.48,1656.1 ; v1(830,1200) 785.5,1200 ; R42.1@833.62,1000 C30.1@833.62,1055 ; C13.1@871.53,2455 820,2455 ; v1(875,1055) C30.1@833.62,1055 ; CN1.6@908.95,4132.28 905,4132.28 v1(905,4035) 905,3990 945,3950 ; LD4.2@925,2733.46 925,2862 ; C17.1@935,2078.47 C16.2@860,2078.47 800,2078.47 ; C9.2@935,3226.38 935,3187.13 v1(932.87,3185) 815,3185 ; U2.35@936.42,3723.23 936.42,3779.3 943.62,3786.5 C5.1@943.62,3810 943.62,3845 ; 950,3835 950,3845 943.62,3845 ; 967.34,3976.38 971.38,3976.38 945,3950 ; 986.38,2373.62 1001.61,2358.39 1061.61,2358.39 ; C18.2@1025,2078.47 v1(1025,2120) 1025,2155 800,2155 ; C10.2@1025,3226.38 1025,3192.13 1022.87,3190 v1(1025,3190) 1077.13,3190 ; v1(1035,4205) 1036.89,4205 CN1.5@1036.89,4134.25 ; U4.63@1047.05,1942.52 1047.05,1900 v1@1052.05,1895 ; v1(1050,1895) v1@1052.05,1895 ; v1(1050,3455) 1054.53,3455 U2.8@1054.53,3376.77 ; U3.12@1061.61,2390.87 1061.61,2358.39 ; v1(1065,2600) 1066.54,2598.46 LD6.2@1066.54,2525 ; v1(1065,2815) LD3.2@1065,2875 ; LD3.2@1066.54,2875 LD3.2@1065,2875 ; C11.1@1075,3226.38 1075,3192.13 1077.13,3190 ; U3.11@1087.2,2390.87 1087.2,2358.39 ; R33.2@1100,2073.62 v1(1100,2120) ; U3.10@1112.8,2390.87 1112.8,2358.39 ; U3.9@1138.39,2390.87 1138.39,2358.39 ; U3.8@1170.87,2358.39 1138.39,2358.39 ; C12.1@1175,3226.38 1175,3192.13 v1@1157.87,3175 ; U2.20@1198.23,3579.53 1290,3579.53 1294.53,3579.53 ; U2.23@1198.23,3638.58 1253.5,3638.58 1256.42,3638.58 ; v1@1255,1263.5 v1(1255,1265) C28.1@1255,1305 ; v1(1260,3585) 1290,3585 1300,3585 ; v1(1265,1050) C31.1@1298.5,1050 ; LD5.2@1275,2733.46 1275,3175 ; 1290,3598.04 C7.1@1290,3626.38 ; C31.1@1301.38,1050 C31.1@1298.5,1050 ; 1305,1263.5 1305,1265 ; 1310.5,1265 1314,1265 1314,1270 ; 1314,1305 1314,1270 ; C29.1@1355,1326.53 1355,1270 ; v1(1355,3350) 1355,3240 1341.38,3226.38 R27.1@1300,3226.38 1300,3175 1275,3175 ; C2.1@1370,3938.62 v1(1370,3995) ; v1(1475,1030) 1415,1090 1304.5,1090 ; LD2.2@1500,4333.46 1501.57,4372.44 v1(1501.57,4375) ; C21.1@1505,1871.53 1476.53,1871.54 1457.95,1852.95 1094.09,1852.95 v1@1052.05,1895 ; C6.2@1508.47,3820 v1(1555,3820) ; C1.1@1508.47,4035 1540,4035 v1(1555,4020) ; v1(1520,715) 1520,711.42 B2.3@1629.13,711.42 ; U1.2@1528.15,3925 1555,3925 1560,3920 1560,3906.38 C3.1@1590,3906.38 1613.62,3906.38 1618.46,3901.54 C4.1@1660,3901.53 v1(1660,3860) ; R17.1@1573.62,3660 v1(1620,3660) ; CN2.6@1608.95,4132.28 1608.95,4230 v1(1610,4230) ; 1695,4042 1695,4048 ; v1(1695,4140) v1@1695,4134.25 ; 1718.58,711.42 1745,685 1745,645 1790,600 P2.33@1850,600 1955,600 1990,635 1990,3700 ; R11.2@1735,3971.38 v1@1735,3937.13 ; CN2.5@1736.89,4134.25 v1@1695,4134.25 ; 1750,3935 v1(1730,3935) ; 1750,3937.13 v1@1735,3937.13 ; TP1.1@2050,3900 2006,3856 1898,3856 1873.5,3880.5 1730,3880.5 v1(1730,3935) ; 542.5,1890 540,1887.5 540,1755 588.5,1706.5 616.5,1706.5 ; 616.5,1706.5 552,1642 552,1232.5 617,1167.5 785.5,1167.5 ; 740,3275 740,3250 805,3185 815,3185 ; 785.5,1167.5 785.5,1200 ; 785.5,1167.5 787.5,1167.5 833.62,1121.38 C30.1@833.62,1055 ; v1@795,1945 800,1950 800,2078.47 ; 800,2078.47 800,2155 ; 800,2155 800,2410 820,2430 820,2455 ; 815,3185 815,3075 850,3040 870,3040 ; 870,3040 1122.87,3040 1152.87,3070 v1@1152.87,3170 ; 925,2862 938,2875 LD3.2@1065,2875 ; v1@940,3845 943.62,3845 ; v1@940,3845 930,3845 v1(930,3850) v1@940,3850 ; v1@940,3845 v1@940,3850 ; v1@940,3850 943.62,3850 943.62,3845 ; v1@940,3850 940,3945 945,3950 ; 1061.61,2358.39 1087.2,2358.39 ; 1077.13,3190 1092.13,3175 v1(1150,3175) ; 1087.2,2358.39 1112.8,2358.39 ; 1112.8,2358.39 1138.39,2358.39 ; v1(1150,3175) 1150,3167.13 v1@1152.87,3170 ; v1(1150,3175) v1@1157.87,3175 ; v1@1152.87,3170 v1@1157.87,3175 ; v1@1157.87,3175 1275,3175 ; C31.1@1298.5,1050 1304.5,1056 1304.5,1090 ; 1304.5,1090 1304.5,1101 1356,1152.5 1356,1270 1355,1270 ; 1314,1270 1355,1270 ; 1695,4048 v1@1695,4134.25 ; 1695,4048 1702.5,4040.5 1702.5,3944 1709.5,3944 1718.5,3935 v1(1730,3935) ; v1(1730,3935) 1730,3937.13 v1@1735,3937.13
  TOP w11.81: P2.2@1850,3700 1897,3653
  TOP w19.68: v1(1025,1235) C26.1@1025,1310 ; v1(1145,1235) C27.1@1145,1305 ; v1@1255,1263.5 1256.5,1265 1305,1265 1310.5,1265
  Bottom w7.87: v1@595,1895 595,1890 591.5,1890 594.5,1887 595,1887.5 737.5,1887.5 v1@790,1940 ; v1@600,1890 v1(600,1895) v1@603,1895 ; v1(625,1055) v1(875,1055) 880,1050 v1(1265,1050) ; v1(665,1755) 665,1729.5 674.5,1720 v1(815,1720) ; v1(705,1570) 705,1570.5 709.5,1575 SB24.2@771.38,1575 ; 737.5,1890 737.5,1902.54 743.46,1908.5 ; v1(740,3325) 740,3420 v1(700,3460) 685,3475 685,3550 v1(750,3615) 835,3700 1005,3700 ; 774.96,1940 v1@790,1940 ; v1(795,1940) v1@790,1940 ; v1(805,4365) 905,4365 v1(905,4035) 940,4035 1035,4130 v1(1035,4205) 1050,4205 1085,4240 1085,4280 1160,4355 1530,4355 ; v1(810,2590) v1(810,2870) v1(810,2980) ; v1(830,1200) 830,1235 v1(1025,1235) ; v1(930,3850) 930,3845 v1@940,3845 ; v1(932.87,3185) 932.87,3272.87 960,3300 SB5.1@960,3325.32 ; 1025,1220 v1(1025,1235) ; v1(1050,1895) 1050,2095 v1(1025,2120) v1(1100,2120) ; v1(1050,3455) 1050,3495 1005,3540 1005,3700 ; v1(1065,2600) v1(1065,2815) ; C32.1@1105,3623.62 1105,3700 ; 1145,1220 v1(1145,1235) v1(1025,1235) ; v1(1260,3585) 1260,3680 1240,3700 1145,3700 ; v1(1355,3350) SB6.2@1401.38,3350 1401.38,3381.89 ; v1(1370,3995) 1530,3995 v1(1555,4020) 1660,3915 v1(1660,3860) ; 1401.57,3314.96 SB6.2@1401.57,3350.39 ; v1(1475,1030) 1478,1030 1520,988 v1(1520,715) ; v1(1501.57,4375) 1501.57,4372.44 1525,4360 1530,4355 ; v1(1555,3820) 1620,3820 ; v1(1620,3660) 1620,3820 ; v1(1695,4140) 1700,4140 v1(1610,4230) 1555,4285 1555,4330 1530,4355 ; v1(1730,3935) 1750,3935 1675,3860 v1(1660,3860) ; v1@940,3845 950,3845 950,3835 ; v1@940,3845 950,3835 ; 950,3835 970,3815 1125,3815 1145,3795 1145,3700 ; 1005,3700 1105,3700 ; 1105,3700 1145,3700 ; 1620,3820 1625,3825 ; 1620,3820 1620,3825 1625,3825 ; 1625,3825 v1(1660,3860)
  other v1: 1015,2417.32
  other v2: 750,800 1450,800 922.83,805.51 1296.85,805.51 44.88,809.45 588.19,809.45 1611.81,809.45 2143.31,848.82 647.24,966.93 1552.76,966.93 450.39,1045.67 1592.13,1085.04 50,1150 500,1150 706.3,1222.83 2143.31,1242.52 450.39,1281.89 1572.44,1380.32 509.45,1419.69 50,1550 1277.17,1636.22 2143.31,1655.91 1100,1675.59 1690.55,1675.59 548.82,1734.65 1178.74,1793.7 903.15,1911.81 50,1950 1690.55,1951.18 2143.31,2049.61 509.45,2207.09 607.87,2207.09 765.35,2226.77 1552.76,2285.83 50,2300 706.3,2443.31 2143.31,2443.31 804.72,2462.99 450.39,2482.68 1296.85,2522.05 863.78,2561.42 981.89,2581.1 450.39,2600.79 1552.76,2600.79 1336.22,2620.47 50,2650 1355.91,2797.64 1552.76,2797.64 863.78,2817.32 2143.31,2837.01 627.56,2876.38 1218.11,2876.38 548.82,3033.86 745.67,3033.86 50,3050 1355.91,3053.54 942.52,3073.23 1001.57,3073.23 1395.28,3171.65 2143.31,3250.39 50,3450 430.71,3466.93 1040.94,3525.98 1143.31,3573.23 2143.31,3663.78 1729.92,3722.83 509.45,3742.52 50,3750 1237.8,3781.89 489.76,3900 706.3,3900 1454.33,3919.69 2143.31,4057.48 300,4150 1808.66,4234.65 1001.57,4313.39 1178.74,4313.39 1690.55,4313.39 1907.09,4313.39 2143.31,4352.76
I2C2_SCL: CN3.3 P1.30 R2.1 U4.29 | length 5785.3
  TOP w6.5: v1(410,4200) CN3.3@496.85,4200 R2.1@601.38,4200 ; U4.29@1263.58,1507.48 1263.58,1545 1288.58,1570 1340,1570 1370,1540 v1(1395,1540)
  Bottom w6.5: P1.30@350,900 P1.30@348,902 ; v1(410,4200) 365,4245 365,4280 320,4325 240,4325 190,4275 190,3990 250,3930 250,1000 P1.30@348,902 ; v1(1395,1540) 1395,1494 1415,1474 1415,1126 1344.5,1055.5 1344.5,943 1303.5,902 P1.30@348,902
I2C2_SDA: CN3.1 P1.31 R1.1 U4.30 | length 5916.6
  TOP w6.5: v1(390,4305) 496.85,4305 CN3.1@496.85,4300 R1.1@601.38,4300 ; U4.30@1283.27,1507.48 1283.27,1543.27 1295,1555 1330,1555 1375,1510 v1(1420,1510)
  Bottom w6.5: v1(390,4305) 345,4350 235,4350 165,4280 165,3975 230,3910 230,920 P1.31@350,800 437,887 1313.5,887 1365,938.5 1365,1050 1430,1115 1430,1500 v1(1420,1510)
LD_D: P2.28 R31.1 U4.38 | length 1507.9
  TOP w6.5: v1(1365,2225) v1@1367.5,2222.5 ; U4.38@1392.52,1675.79 1474.21,1675.79 v1(1480,1670) 1743,1407 1743,1206 1849,1100 P2.28@1850,1100
  TOP w7.87: R31.1@1325,2266.53 1325,2227 1329.5,2222.5 v1@1367.5,2222.5
  Bottom w6.5: v1(1365,2225) 1360,2220 1360,1790 v1(1480,1670)
LD_L: P2.27 R32.1 U4.39 | length 1392.9
  TOP w6.5: U4.39@1392.52,1695.47 1494.53,1695.47 v1(1510,1680) 1765.5,1424.5 1765.5,1284.5 P2.27@1850,1200 ; v1(1410,2225) 1415,2225 v1@1416,2226
  TOP w7.87: R32.1@1410,2266.53 1410,2226 v1@1416,2226
  Bottom w6.5: v1(1410,2225) 1415,2225 1415,1765 1500,1680 v1(1510,1680)
LD_R: P2.26 R30.1 U4.40 | length 1467.2
  TOP w6.5: U4.40@1392.52,1715.16 1514.84,1715.16 v1(1520,1710) 1787.5,1442.5 1787.5,1362.5 P2.26@1850,1300 ; v1(1475,2375) R30.1@1475,2431.53
  Bottom w6.5: v1(1475,2375) 1475,2376.5 1431.5,2333 1431.5,1778.5 1500,1710 v1(1520,1710)
LD_U: P2.29 R29.1 U4.37 | length 1729.8
  TOP w6.5: v1(1335,1745) 1335,1675 1353.9,1656.1 1455,1656.1 1721,1390.1 1721,1130.5 1850,1001.5 P2.29@1850,1000 ; v1(1390,2390) R29.1@1390,2431.53
  Bottom w6.5: v1(1335,1745) 1340,1745 1340,2339.5 1390,2389.5 v1(1390,2390)
LED_STLINK: R5.1 R6.1 U2.30 | length 618.5
  TOP w6.5: R5.1@745,4031.38 R6.1@805,4031.38 805,3945 833,3917 833,3794 867,3760 v1(880,3760) ; U2.30@1034.84,3723.23 1034.84,3769.84 v1(1050,3785)
  Bottom w6.5: v1(880,3760) 1024,3760 1049,3785 v1(1050,3785)
LS_P1: LS1.1 R38.2 | length 3058.9
  TOP w7.87: LS1.1@151.18,295 135,295 135,505 150,520 745,520 780,555 v1(1055,555) 1060,560 1060,1006 965,1101 R38.2@965,1151.38 ; v1(1180,555) 1180,550 1429,550 1459,520 2050,520 2060,510 2060,295 LS1.1@2048.82,295
  Bottom w7.87: v1(1055,555) 1055,556 1056,555 v1(1180,555)
LS_P2: LS1.2 R39.2 | length 1161.2
  TOP w7.87: LS1.2@777.16,295 777.16,502.16 795.5,520.5 1080.5,520.5 1100,540 1100,1061.5 1090,1071.5 R39.2@1090,1151.38
LS_P3: LS1.3 R40.2 | length 1143.6
  TOP w7.87: R40.2@1200,1151.38 1200,1125 1140,1065 1140,540 1160,520 1405.67,520 1420.67,505 1420.67,295 LS1.3@1422.83,295
MCO: C32.2 R44.2 SB19.1 | length 1849.6
  Bottom w6.5: SB19.1@950,1844.68 950,1877.5 945.5,1882 945.5,2630.5 970,2655 970,3198.5 1081,3309.5 1081,3501 1105,3525 C32.2@1105,3576.38 R44.2@1055,3576.38
MEMS_INT1: P1.12 U3.7 U4.9 | length 1856.7
  TOP w6.5: P1.12@350,2700 377.5,2672.5 792.5,2672.5 1019.5,2445.5 1159.5,2445.5 1210,2395 v1(1210,2350) 1192.8,2332.8 U3.7@1170.87,2332.8 ; U4.9@957.48,1715.16 1007.16,1715.16 1047,1755 v1(1065,1755)
  Bottom w6.5: v1(1065,1755) 1155,1845 1155,2210 1195,2250 1195,2335 v1(1210,2350)
MEMS_INT2: P1.13 U3.6 U4.10 | length 2187
  TOP w6.5: P1.13@350,2600 279.5,2670.5 279.5,2716 313,2749.5 389.5,2749.5 449,2690 793,2690 1023,2460 1169,2460 1238.5,2390.5 1238.5,2323.5 v1@1222.2,2307.2 ; U4.10@957.48,1695.47 1010.47,1695.47 1045,1730 v1(1090,1730) ; U3.6@1170.87,2307.2 v1@1222.2,2307.2 ; v1(1220,2305) v1@1222.2,2307.2
  Bottom w6.5: v1(1090,1730) 1090,1761 1170,1841 1170,2205 1210,2245 1210,2295 v1(1220,2305)
NCS_MEMS_SPI: P1.11 U3.5 U4.8 | length 1957.3
  TOP w6.5: P1.11@350,2800 398,2800 488.5,2709.5 791.5,2709.5 1028,2473 1179,2473 1263,2389 1263,2306.5 1211.5,2255 v1(1170,2255) 1170,2281.61 U3.5@1170.87,2281.61 ; U4.8@957.48,1734.84 1003.34,1734.84 1045,1776.5 v1(1045,1780)
  Bottom w6.5: v1(1045,1780) 1070,1780 1140,1850 1140,2225 v1(1170,2255)
NetB1_2: B1.2 B1.3 R41.2 R42.2 | length 570.5
  TOP w6.5: B1.3@570.87,888.58 673.58,888.58 v1(725,940) R41.2@725,1000 ; R41.2@725,1006.38 R41.2@725,1000 ; R42.2@786.38,1000 R41.2@725,1000 ; B1.2@929.13,888.58 929.13,945 v1(930,945)
  Bottom w6.5: v1(725,940) 930,940 v1(930,945)
NetB2_1: B2.1 B2.4 C31.2 R43.1 SB22.2 | length 1493.1
  TOP w6.5: B2.1@1270.87,888.58 1363.58,888.58 1370.5,895.5 v1(1375,900) ; R43.1@1348.62,995 1385,995 1395,1005 v1(1395,1050) C31.2@1348.62,1050
  TOP w7.87: v1@1370.5,895.5 1377.42,888.58 B2.4@1629.13,888.58
  Bottom w6.5: SB22.2@1198.62,1725 1241,1725 1445,1521 1445,1100 v1(1395,1050) 1395,920 v1(1375,900)
NetC1_2: C1.2 U1.4 | length 80.8
  TOP w11.81: U1.4@1421.85,3962.4 1421.85,4011.85 1441.53,4031.54 C1.2@1441.53,4035
NetC2_2: C2.2 C6.1 D3.1 U1.5 | length 208.3
  TOP w11.81: D3.1@1350,3845 1370,3845 ; U1.5@1421.85,3887.6 1373.78,3887.6 C2.2@1370,3891.38 1370,3845 ; C6.1@1441.53,3820 1383.62,3820 1370,3833.62 1370,3845
NetC13_2: C13.2 C34.1 U3.14 | length 292.1
  TOP w6.5: C34.1@938.98,2375.98 938.47,2376.5 C13.2@938.47,2450 ; v1(985,2450) C13.2@938.47,2450 ; v1(990,2335) 990,2332.8 U3.14@1029.13,2332.8 ; C13.2@938.46,2450 C13.2@938.47,2455 C13.2@938.47,2450
  Bottom w6.5: v1(985,2450) 985,2335 v1(990,2335)
NetC19_1: C19.1 R34.2 X2.4 | length 239.6
  TOP w6.5: C19.1@560,2008.47 630.53,2008.47 R34.2@634,2005 ; X2.4@592.01,2131.73 648.5,2075.24 648.5,2019.5 R34.2@634,2005 ; R34.2@630,1998.62 630,2001 R34.2@634,2005
NetC20_1: C20.1 R35.2 X2.1 | length 243.3
  TOP w6.5: X2.1@717.99,2131.73 662,2075.74 662,2016.62 R35.2@680,1998.62 680,2008 680.46,2008.47 C20.1@750,2008.47
NetC22_2: C22.2 R36.2 X3.2 | length 212
  TOP w6.5: X3.2@600.2,1774.64 649.02,1823.47 C22.2@725,1823.47 789.84,1823.47 R36.2@791.38,1825
NetC23_2: C23.2 R37.2 X3.1 | length 334.9
  TOP w6.5: X3.1@600.2,1574.64 600.2,1640.2 638.46,1678.47 C23.2@750,1678.47 749.96,1689.46 791.38,1730.88 R37.2@791.38,1765
NetC30_2: C30.2 R41.1 SB21.2 | length 1164.9
  TOP w6.5: v1(495,1715) 498.5,1715 534.5,1679 534.5,1208 622,1120.5 691.5,1120.5 725,1087 R41.1@725,1055 ; R41.1@725,1053.62 R41.1@725,1055 ; C30.2@786.38,1055 R41.1@725,1055
  Bottom w6.5: v1(495,1715) 514,1696 696.5,1696 732.5,1660 SB21.2@776.38,1660
NetC34_2: C34.2 R45.2 | length 73.7
  TOP w6.5: R45.2@870.08,2344.49 887.8,2326.77 C34.2@936.42,2326.77
NetCN1_2: CN1.2 R10.1 | length 119.9
  TOP w6.55: CN1.2@1131.39,4134.25 1131.39,4120 1124.5,4113.11 1124.5,4041 1140,4025.5 R10.1@1140,4023.62
NetCN1_3: CN1.3 R8.1 R9.1 | length 169.8
  TOP w6.55: R8.1@1045,4023.62 R9.1@1095,4023.62 1095,4028.5 1108.5,4042 1108.5,4101.89 1099.89,4110.5 CN1.3@1099.89,4134.25
NetCN1_4: CN1.4 R7.1 | length 170.3
  TOP w6.5: R7.1@990,4023.62 990,4044 1004.5,4058.5 1051,4058.5 1068.39,4075.89 CN1.4@1068.39,4134.25
NetCN2_1: CN2.1 D2.1 | length 123.8
  TOP w11.81: CN2.1@1862.89,4134.25 1862.89,4097.11 1910,4050 D2.1@1910,4030
NetCN2_2: CN2.2 R13.1 | length 127.4
  TOP w6.55: CN2.2@1831.39,4134.25 1831.39,4086.89 1824,4079.5 1824,4042.5 1845,4021.5 R13.1@1845,4018.62
NetCN2_3: CN2.3 R12.1 | length 128.9
  TOP w6.55: R12.1@1790,4018.62 1790,4022 1811,4043 1811,4080 1799.89,4091.11 CN2.3@1799.89,4134.25
NetCN2_4: CN2.4 R11.1 | length 129.5
  TOP w6.5: R11.1@1735,4018.62 1735,4048.23 1768.39,4081.61 CN2.4@1768.39,4134.25
NetCN4_1: CN4.1 D4.1 R18.1 | length 172.8
  TOP w6.5: CN4.1@550,3600 R18.1@651.38,3600 651.38,3650 D4.1@630,3650
NetCN4_2: CN4.2 R20.1 | length 101.4
  TOP w6.5: CN4.2@550,3500 R20.1@651.38,3500
NetCN4_4: CN4.4 R21.1 | length 106.4
  TOP w6.5: CN4.4@550,3300 R21.1@656.38,3300
NetCN4_5: CN4.5 R24.1 | length 106.4
  TOP w6.5: CN4.5@550,3200 R24.1@656.38,3200
NetCN4_6: CN4.6 R28.1 | length 106.4
  TOP w6.5: CN4.6@550,3100 R28.1@656.38,3100
NetCN5_1: CN5.1 SB1.1 SB2.2 | length 206.7
  Bottom w6.5: SB1.1@1444.68,3550 CN5.1@1550,3550 SB2.2@1651.38,3550
NetCN5_2: CN5.2 SB3.1 SB4.2 | length 206.7
  Bottom w6.5: SB3.1@1444.68,3450 CN5.2@1550,3450 SB4.2@1651.38,3450
NetCN5_3: CN5.3 SB6.1 SB7.2 | length 206.7
  Bottom w6.5: SB6.1@1444.68,3350 CN5.3@1550,3350 SB7.2@1651.38,3350
NetCN5_4: CN5.4 SB8.1 SB9.2 | length 206.7
  Bottom w6.5: SB8.1@1444.68,3250 CN5.4@1550,3250 SB9.2@1651.38,3250
NetD4_2: D4.2 R15.1 | length 65.6
  TOP w6.5: D4.2@720,3650 721.38,3651.38 R15.1@721.38,3715
NetL1_2: L1.2 SB26.1 | length 100.5
  TOP w11.81: v1(630,1370) 675,1370 L1.2@675,1375
  Bottom w11.81: SB26.1@590,1395.32 615.31,1370 v1(630,1370)
NetLD1_2: LD1.2 R6.2 | length 112.8
  TOP w6.5: LD1.2@804.53,4190.94 805,4190.94 R6.2@805,4078.62
NetLD1_3: LD1.3 R5.2 | length 112.8
  TOP w6.5: R5.2@745,4078.62 745,4190.94 LD1.3@745.47,4190.94
NetLD1_4: LD1.4 R4.1 | length 253.4
  TOP w6.5: R4.1@690,4078.62 690,4246 745.47,4301.47 LD1.4@745.47,4309.06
